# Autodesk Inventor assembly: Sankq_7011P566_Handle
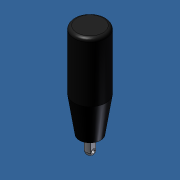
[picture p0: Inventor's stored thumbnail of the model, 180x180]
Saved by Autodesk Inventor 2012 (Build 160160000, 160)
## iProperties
Created: 2013-10
Part Number: Sankq_7011P566_Handle
Document SubType Name: Assembly
Designer: Admin
Author: Admin
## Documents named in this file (5)
- C:\Andys Backup Data\ANDY'S INVENTOR\INVENTOR LIBRARIES\PARTS LIBRARY\HYDRAULIC VERTICAL ADJUSTMENT\27.9001Telescoping Twin Leg System\SUBCOMPONENTS\Qxx18_crank pump\Sankq_7011P566_Handle.iam
- C:\Andys Backup Data\ANDY'S INVENTOR\INVENTOR LIBRARIES\PARTS LIBRARY\HYDRAULIC VERTICAL ADJUSTMENT\27.9001Telescoping Twin Leg System\SUBCOMPONENTS\Qxx18_crank pump\NONE_2.ipt
- C:\Andys Backup Data\ANDY'S INVENTOR\INVENTOR LIBRARIES\PARTS LIBRARY\HYDRAULIC VERTICAL ADJUSTMENT\27.9001Telescoping Twin Leg System\SUBCOMPONENTS\Qxx18_crank pump\NONE_3.ipt
- C:\Andys Backup Data\ANDY'S INVENTOR\INVENTOR LIBRARIES\PARTS LIBRARY\HYDRAULIC VERTICAL ADJUSTMENT\27.9001Telescoping Twin Leg System\SUBCOMPONENTS\Qxx18_crank pump\NONE_4.ipt
- C:\Andys Backup Data\ANDY'S INVENTOR\INVENTOR LIBRARIES\PARTS LIBRARY\HYDRAULIC VERTICAL ADJUSTMENT\27.9001Telescoping Twin Leg System\SUBCOMPONENTS\Qxx18_crank pump\NONE_5.ipt
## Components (4 placed, 4 different names)
1. NONE_2:1
2. NONE_3:1
3. NONE_4:1
4. NONE_5:1
